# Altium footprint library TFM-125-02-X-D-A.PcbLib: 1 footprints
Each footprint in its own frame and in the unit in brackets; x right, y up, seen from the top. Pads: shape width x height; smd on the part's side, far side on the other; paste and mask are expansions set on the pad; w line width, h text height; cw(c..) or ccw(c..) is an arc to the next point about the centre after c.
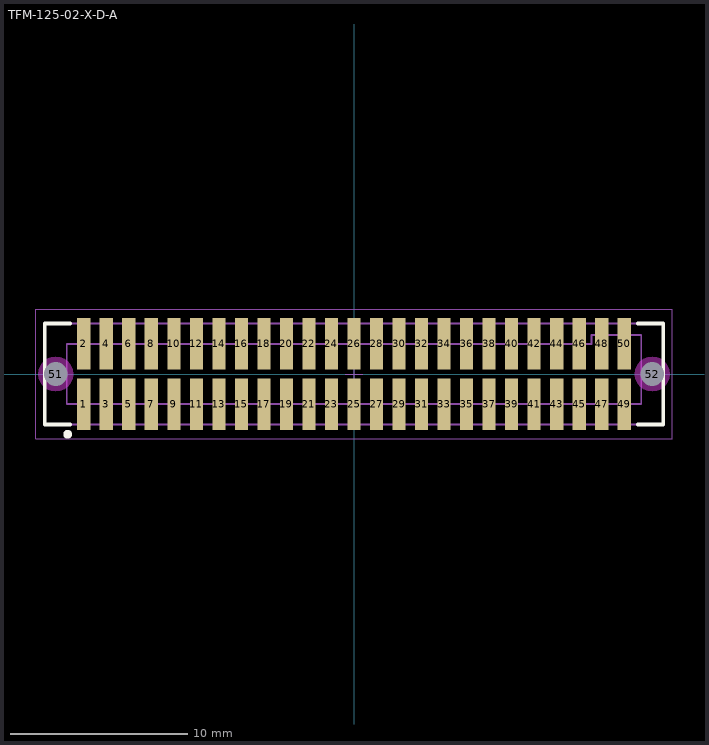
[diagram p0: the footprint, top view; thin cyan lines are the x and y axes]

## TFM-125-02-X-D-A [mm] "1.27mm pitch, 50 pin, terminal strip; w/alignment pins, SMT"
height 5.72
pads (52):
  rect 0.75x2.9 smd mask+0: 1(-15.24,-1.714) 2(-15.24,1.714) 3(-13.97,-1.714) 4(-13.97,1.714) 5(-12.7,-1.714) 6(-12.7,1.714) 7(-11.43,-1.714) 8(-11.43,1.714) 9(-10.16,-1.714) 10(-10.16,1.714) 11(-8.89,-1.714) 12(-8.89,1.714) 13(-7.62,-1.714) 14(-7.62,1.714) 15(-6.35,-1.714) 16(-6.35,1.714) 17(-5.08,-1.714) 18(-5.08,1.714) 19(-3.81,-1.714) 20(-3.81,1.714) 21(-2.54,-1.714) 22(-2.54,1.714) 23(-1.27,-1.714) 24(-1.27,1.714) 25(0,-1.714) 26(0,1.714) 27(1.27,-1.714) 28(1.27,1.714) 29(2.54,-1.714) 30(2.54,1.714) 31(3.81,-1.714) 32(3.81,1.714) 33(5.08,-1.714) 34(5.08,1.714) 35(6.35,-1.714) 36(6.35,1.714) 37(7.62,-1.714) 38(7.62,1.714) 39(8.89,-1.714) 40(8.89,1.714) 41(10.16,-1.714) 42(10.16,1.714) 43(11.43,-1.714) 44(11.43,1.714) 45(12.7,-1.714) 46(12.7,1.714) 47(13.97,-1.714) 48(13.97,1.714) 49(15.24,-1.714) 50(15.24,1.714)
  round 1 hole 1.35 unplated mask+0: 51(-16.828,0) 52(16.828,0)
Top Overlay:
  circle w0.25: c-16.15,-3.4 r0.125
  lines w0.2: -16,-2.85 -17.45,-2.85 -17.45,2.85 -16,2.85 ; 16,-2.85 17.45,-2.85 17.45,2.85 16,2.85
Keep-Out Layer:
  pour cut-out: 17.811,0 17.778,0.255 17.679,0.492 17.523,0.695 17.319,0.852 17.082,0.95 16.828,0.983 16.573,0.95 16.336,0.852 16.132,0.695 15.976,0.492 15.878,0.255 15.844,0 15.878,-0.255 15.976,-0.492 16.132,-0.695 16.336,-0.852 16.573,-0.95 16.828,-0.983 17.082,-0.95 17.319,-0.852 17.523,-0.695 17.679,-0.492 17.778,-0.255
  pour cut-out: -15.844,0 -15.878,0.255 -15.976,0.492 -16.132,0.695 -16.336,0.852 -16.573,0.95 -16.828,0.983 -17.082,0.95 -17.319,0.852 -17.523,0.695 -17.679,0.492 -17.778,0.255 -17.811,0 -17.778,-0.255 -17.679,-0.492 -17.523,-0.695 -17.319,-0.852 -17.082,-0.95 -16.828,-0.983 -16.573,-0.95 -16.336,-0.852 -16.132,-0.695 -15.976,-0.492 -15.878,-0.255
Mechanical 13:
  circle w0.1: c-16.139,-3.366 r0.127
  lines w0.1: -17.45,-2.85 -17.45,2.85 17.45,2.85 17.45,-2.85 -17.45,-2.85 ; -16.2,-1.7 -16.2,1.7 13.4,1.7 13.4,2.2 16.2,2.2 16.2,-1.7 -16.2,-1.7
  text ".Designator" at 0,-0.127 h1.52
Mechanical 15:
  lines w0.05: -0.5,0 0.5,0 ; 0,-0.5 0,0.5 ; -17.95,-3.65 -17.95,3.65 17.95,3.65 17.95,-3.65 -17.95,-3.65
